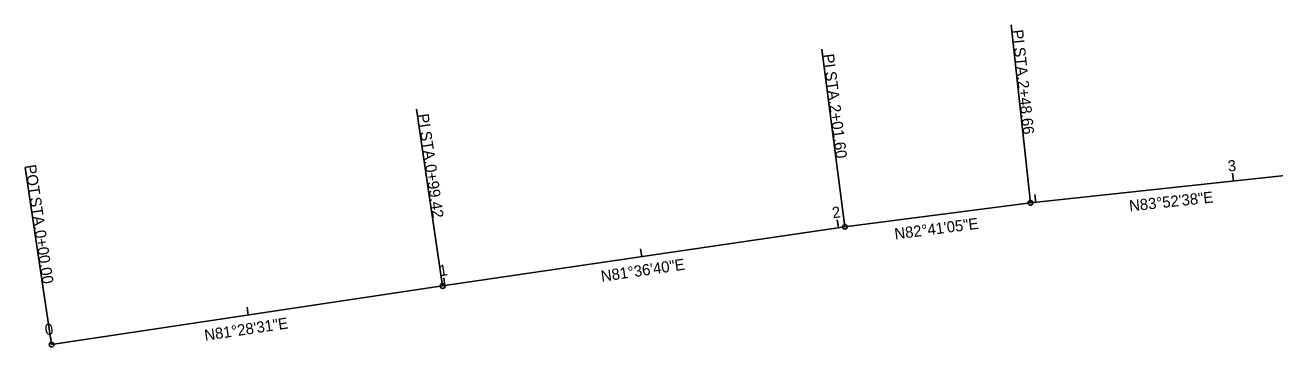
# Model space of a CAD drawing. Extents: x 1369241 to 1370511, y 405823 to 406278.
# Drawn here: x 1369240.8 to 1369555.1, y 405851 to 405931.9 of the extents above; entities that cross this region are included whole.
import ezdxf

# ---------------------------------------------------------------- set-up
doc = ezdxf.new("R2010")
doc.units = 0
doc.layers.add('MD_P_CSS_B', color=7, linetype='Continuous')
doc.layers.add('PM_P_Crosswalk', color=7, linetype='Continuous')

msp = doc.modelspace()

# ---------------------------------------------------------------- linework, layer by layer
at = {"layer": 'MD_P_CSS_B'}
for p, q in [((1369493.58, 405887.19), (1369565.1, 405894.87)), ((1369544.63, 405892.67), (1369544.42, 405894.66)), ((1369446.9, 405881.2), (1369493.58, 405887.19)), ((1369494.91, 405887.34), (1369494.7, 405889.33)), ((1369345.82, 405866.3), (1369446.9, 405881.2)), ((1369445.32, 405880.97), (1369445.03, 405882.95)), ((1369395.86, 405873.67), (1369395.57, 405875.65)), ((1369346.39, 405866.38), (1369346.1, 405868.36)), ((1369247.5, 405851.56), (1369345.82, 405866.3)), ((1369296.94, 405858.97), (1369296.65, 405860.95)), ((1369247.5, 405851.56), (1369247.2, 405853.54))]:
    msp.add_line(p, q, dxfattribs=at)
at = {"layer": 'PM_P_Crosswalk'}
for p, q in [((1369493.58, 405887.19), (1369488.78, 405931.94)), ((1369446.9, 405881.2), (1369441.17, 405925.84)), ((1369345.82, 405866.3), (1369339.26, 405910.81)), ((1369247.5, 405851.56), (1369240.83, 405896.06))]:
    msp.add_line(p, q, dxfattribs=at)
for centre in [(1369493.58, 405887.19), (1369446.9, 405881.2), (1369345.82, 405866.3), (1369247.5, 405851.56)]:
    msp.add_circle(centre, 0.6, dxfattribs=at)

# ---------------------------------------------------------------- texts
at = {"layer": 'MD_P_CSS_B'}
for s, rotation, p in [('3', 6.1227, (1369543.33, 405895.05)), ('2', 8.389, (1369443.92, 405883.29)), ('1', 8.389, (1369345.12, 405868.72)), ('0', 8.5247, (1369246.03, 405853.87))]:
    msp.add_text(s, height=2.8, rotation=rotation, dxfattribs=at).set_placement(p)
at = {"layer": 'PM_P_Crosswalk'}
for s, rotation, p in [('PI', 276.1227, (1369488.96, 405930.62)), ('PI', 277.3151, (1369441.39, 405924.51)), (' STA. ', 276.1227, (1369489.32, 405927.25)), (' STA. ', 277.3151, (1369441.82, 405921.15)), ('2+48.66', 276.1227, (1369490.33, 405917.85)), ('2+01.60', 277.3151, (1369443.02, 405911.77)), ('PI', 278.389, (1369339.5, 405909.43)), (' STA. ', 278.389, (1369340, 405906.07)), ('POT', 278.5247, (1369240.78, 405896.62)), ('0+99.42', 278.389, (1369341.38, 405896.72)), ('N83°52\'38"E', 6.1227, (1369518.55, 405885.05)), (' STA. ', 278.5247, (1369241.85, 405889.5)), ('N82°41\'05"E', 7.3151, (1369459.58, 405877.99)), ('0+00.00', 278.5247, (1369243.25, 405880.16)), ('N81°36\'40"E', 8.389, (1369385.82, 405867.34)), ('N81°28\'31"E', 8.5247, (1369286.13, 405852.5))]:
    msp.add_text(s, height=2.8, rotation=rotation, dxfattribs=at).set_placement(p)

doc.saveas('drawing.dxf')
